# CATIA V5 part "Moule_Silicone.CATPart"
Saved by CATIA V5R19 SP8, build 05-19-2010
Part number: Moule
Material "Silicone 50": density 0.96 kg/m3, Young's modulus 6.7e+06 Pa
Material "Silicone 50": density 0.96 kg/m3, Young's modulus 6.7e+06 Pa
Bounding box of the stored display mesh (mm): x -5 to 15, y -30 to 30, z -30 to 30
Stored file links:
  D:\Documents\1_Travail\2- 2I2D\6 -  Ressources ITEC\Ressources Logiciels\Catia\Moule_Silicone.CATPart
  D:\Documents\1_Travail\3 -  Supports d'étude\Bonhomme_ITEC\Activités pédagogiques_Bonhomme ITEC\Activité_4-9.2h_Conception_moule\Activité 4-9.2h_Conception moule silicone\Bonhomme ITEC.CATPart
  C:\Program Files\Dassault Systemes\B19\win_b64\startup\materials\French\Catalog.CATMaterial
  D:\Travail\30 -  IUT\SICAM\CAPOT_BORNIER_15-04-14.CATPart
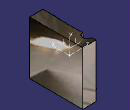
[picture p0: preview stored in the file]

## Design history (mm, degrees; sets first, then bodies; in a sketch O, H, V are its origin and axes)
Parameters
  `Epaisseur du demi-moule arrière` = 15 mm
  Hauteur = 60 mm
  Largeur = 60 mm
  `Epaisseur du demi-moule avant` = 15 mm
AxisSystem1: origin (0, 0, 0), X (0, -1, 0), Y (0, 0, 1), Z (-1, 0, 0)
Set1 "Esquisses paramétrables"
  Sketch1 "Bloc" on yz-plane, origin (0, 0, 0), H (0, 1, 0), V (0, 0, 1)
    line L1 (30, 30) -> (30, -30)
    line L2 (30, -30) -> (-30, -30)
    line L3 (-30, -30) -> (-30, 30)
    line L4 (-30, 30) -> (30, 30)
    distance L4 L2 = 60 {= Hauteur}
    distance L1 L3 = 60 {= Largeur}
    vertical: L1 V, L3 V
    horizontal: L2 H, L4 H
    equidistance: L1 L3 O, L2 L4 O
  Sketch2 "Plots de centrage" on yz-plane, origin (0, 0, 0), H (0, 1, 0), V (0, 0, 1)
    circle A1 centre (-22, 22) radius 4
    point P1 (-22, 22)
    reference projected line E1 (-30, 50) -> (-30, -50) from Sketch1.L3
    reference projected line E2 (50, 30) -> (-50, 30) from Sketch1.L4
    reference intersected line E3 through (0, 0) direction (0, 1) from zx-plane
    circle A2 centre (-22, -22) radius 4
    circle A3 centre (22, -22) radius 4
    radius A1 = 4
    distance P1 E1 = 8 {= Sketch2.radius(A1) *2}
    distance P1 E2 = 8 {= Sketch2.radius(A1) *2}
    symmetry: A1 A2 H, A2 A3 E3
  Sketch3 "Entonnoir de coulée" on yz-plane, origin (0, 0, 0), H (0, 1, 0), V (0, 0, 1)
    line L1 (22, 18.7821) -> (22, 17.2821)
    line L2 (22, 17.2821) -> (20, 17.2821)
    point P3 (20, 17.2821)
    point P4 (20, 30)
    line L3 (20, 30) -> (25, 30)
    point P5 (25, 30)
    arc A1 centre (22, 20) radius 1.2179 from (23.1994, 19.7885) to (22, 18.7821) cw
    point P6 (22, 20)
    reference projected line E1 (35, 30) -> (-35, 30) from edge [face of Pad3 from Sketch1.L4 | start face of Pad3]
    line L4 (25, 30) -> (23.1994, 19.7885)
    axis line L5 (20, 17.2821) -> (20, 43.0292)
    reference projected line E2 (30, -35) -> (30, 35) from edge [face of Pad3 from Sketch1.L1 | start face of Pad3]
    reference intersected line E3 (-40, 30) -> (40, 30) from face of Pad1 from Sketch1.L4
    length L1 = 1.5
    distance L5 E2 = 10
    angle L5 L4 = 10
    distance L5 L1 = 2
    "Radius" P5 L5 = 5
    distance P6 E3 = 10
    vertical: L1 V, L5 V
    horizontal: L2 H, L3 H
    coincidence: L3 E1, P6 L1, L5 P4
    tangency: L4 A1
  Sketch4 "Trou de coulée_Guide" on yz-plane, origin (0, 0, 0), H (0, 1, 0), V (0, 0, 1)
    point P1 (20, 17.2821)
    line L1 (20, 17.2821) -> (20, -11.6152)
    line L2 (6.6152, -25) -> (3, -25)
    point P2 (0, -25)
    line L3 (0, -22) -> (0, -18.5526)
    reference projected point E1 (20, 17.2821) from Sketch3.P3
    reference projected line E2 (-35, -30) -> (35, -30) from edge [face of Pad3 from Sketch1.L2 | start face of Pad3]
    arc A1 centre (3, -22) radius 3 from (0, -22) to (3, -25) ccw
    line L4 (18.2426, -15.8579) -> (10.8579, -23.2426)
    arc A2 centre (14, -11.6152) radius 6 from (18.2426, -15.8579) to (20, -11.6152) ccw
    arc A3 centre (6.6152, -19) radius 6 from (6.6152, -25) to (10.8579, -23.2426) ccw
    reference projected point E3 (22, -22) from edge
    distance L2 E2 = 5
    radius A1 = 3
    radius A2 = 6
    radius A3 = 6
    distance L4 E3 = 7
    angle L4 L1 = 45
    vertical: L1 V, L3 V
    coincidence: P2 V, P1 E1, L3 P2, L2 P2
    horizontal: L2 H
    tangency: A1 L3, A1 L2, A2 L4, A2 L1, A3 L2, A3 L4
  Sketch5 "Trou de coulée_Profil" on xy-plane, origin (0, 0, 0), H (1, 0, 0), V (0, 1, 0)
    circle A1 centre (0, 20) radius 2
    reference projected circle E1 centre (0, 20) radius 2 from edge [face of Groove2 from Sketch3.L1 | face of Groove2 from Sketch3.A1]
    coincidence: A1 E1
  Sketch6 "Cannaux doubles_Guide" on yz-plane, origin (0, 0, 0), H (0, 1, 0), V (0, 0, 1)
    point P1 (-8.8498, -7.3684)
    line L1 (-8.8498, -7.3684) -> (-5.9091, -18.2518)
    line L2 (-3.9924, -19.73) -> (0, -19.7581)
    point P2 (0, -19.7581)
    arc A1 centre (-3.9783, -17.7301) radius 2 from (-3.9924, -19.73) to (-5.9091, -18.2518) cw
    point P3 (-3.9924, -19.73)
    point P4 (-5.9091, -18.2518)
    reference intersected line E1 through (0, 0) direction (0, 1) from zx-plane
    point P8 (0, -19.7581)
    point P9 (3.9924, -19.73)
    line L3 (3.9924, -19.73) -> (0, -19.7581)
    point P10 (5.9091, -18.2518)
    arc A2 centre (3.9783, -17.7301) radius 2 from (3.9924, -19.73) to (5.9091, -18.2518) ccw
    point P12 (8.8498, -7.3684)
    line L4 (8.8498, -7.3684) -> (5.9091, -18.2518)
    reference projected point E2 (0, -18.7581) from Sketch7.L4
    reference projected point E3 (0, -20.7581) from Sketch7.L2
    radius A1 = 2
    coincidence: P2 V, P2 P8
    tangency: A1 L2, A1 L1
    symmetry: P2 P8 E1, P3 P9 E1, L2 L3 E1, P4 P10 E1, A1 A2 E1, P1 P12 E1, L1 L4 E1
    equidistance: E2 E3 P2
  Sketch7 "Cannaux doubles_Profil" on zx-plane, origin (0, 0, 0), H (-1, 0, 0), V (0, 0, 1)
    point P1 (0, -19.7581)
    line L1 (0.5, -18.7581) -> (0.5, -20.7581)
    line L2 (0.5, -20.7581) -> (-0.5, -20.7581)
    line L3 (-0.5, -20.7581) -> (-0.5, -18.7581)
    line L4 (-0.5, -18.7581) -> (0.5, -18.7581)
    reference intersected line E1 (0, -40) -> (0, 40) from start face of Pad3
    distance L3 L1 = 1
    distance L4 L2 = 2
    vertical: L1 V, L3 V
    horizontal: L2 H, L4 H
    equidistance: L1 L3 P1, L2 L4 P1
    coincidence: P1 E1
  Sketch8 "Event" on yz-plane, origin (0, 0, 0), H (0, 1, 0), V (0, 0, 1)
    point P1 (0, 30)
    line L1 (0, 30) -> (-12, 30)
    point P2 (-12, 30)
    point P3 (-1, 22.6077)
    line L2 (-1, 22.6077) -> (-1, 20.6077)
    point P4 (-1, 20.6077)
    line L3 (-1, 20.6077) -> (0, 20.6077)
    point P5 (0, 20.6077)
    reference projected line E1 (50, 30) -> (-50, 30) from edge [face of Pad3 from Sketch1.L4 | start face of Pad3]
    reference intersected line E2 through (0, 0) direction (0, 1) from zx-plane
    point P8 (0, 30)
    point P9 (12, 30)
    point P10 (1, 22.6077)
    point P11 (1, 20.6077)
    point P12 (0, 20.6077)
    line L4 (0, 30) -> (12, 30)
    line L5 (12, 30) -> (1, 22.6077)
    line L6 (1, 22.6077) -> (1, 20.6077)
    line L7 (1, 20.6077) -> (0, 20.6077)
    point P13 (-12, 30)
    line L8 (-12, 30) -> (-1, 22.6077)
    length L3 = 1
    length L1 = 12 {= Sketch1.distance(L4 L2) /5}
    length L2 = 2
    coincidence: P1 V, P5 V, L1 E1, P1 P8, P5 P12, P13 P2
    horizontal: L1 H, L3 H
    vertical: L2 V
    symmetry: P1 P8 E2, P2 P9 E2, P3 P10 E2, P4 P11 E2, P5 P12 E2, L1 L4 E2, L2 L6 E2, L3 L7 E2
  Sketch9 "Bloc contre moule" on end face of Pad2, origin (-5, 0, 0), H (0, 1, 0), V (0, 0, 1)
    line L1 (-35, 35) -> (35, 35)
    line L2 (35, 35) -> (35, -35)
    line L3 (35, -35) -> (-35, -35)
    line L4 (-35, -35) -> (-35, 35)
    reference projected line E1 (30, -40) -> (30, 40) from edge [face of Pad1 from Sketch1.L1 | end face of Pad1]
    reference projected line E2 (-30, 40) -> (-30, -40) from edge [face of Pad1 from Sketch1.L3 | end face of Pad1]
    reference projected line E3 (-40, -30) -> (40, -30) from edge [face of Pad1 from Sketch1.L2 | end face of Pad1]
    reference intersected line E4 through (0, 30) direction (1, 0) from face of Pad1 from Sketch1.L4
    distance E1 L2 = 5
    distance L4 E2 = 5 {= Sketch9.distance(E1 L2)}
    distance E3 L3 = 5 {= Sketch9.distance(E1 L2)}
    distance L1 E4 = 5 {= Sketch9.distance(E1 L2)}
    horizontal: L1 H, L3 H
    vertical: L2 V, L4 V
Body1 "Demi-moule Arrière" (main body), material "Silicone 50"
  Pad1 "Bloc": profile Sketch1, direction (1, 0, 0), length 15 {= `Epaisseur du demi-moule arrière`}
  Pad2 "Plots": profile Sketch2, direction (-1, 0, 0), length 5
  Draft1 "Dépouille.plots": PullDir end face of Pad2, Angle 5, SupportToDraft (face of Pad2 from Sketch2.A1; face of Pad2 from Sketch2.A2; face of Pad2 from Sketch2.A3), Neutral start face of Pad1
  Groove1 "Entonnoir de coulée": profile Sketch3, axis Sketch3.L5, angle 360
  Slot1 "Trou de coulée": profile Sketch5, centre curve Sketch4
  Slot2 "Cannaux de coulée": profile Sketch7, centre curve Sketch6
  Pocket1 "Event": profile Sketch8, direction (1, 0, 0), length 0.5
Body2 "Demi-moule Avant", material "Silicone 50"
  Pad3 "Bloc": profile Sketch1, direction (-1, 0, 0), length 15 {= `Epaisseur du demi-moule avant`}
  Pocket2 "Plots": profile Sketch2, direction (-1, 0, 0), length 6
  Draft2 "Dépouille.Plots": PullDir (-1, 0, 0), Angle -5, SupportToDraft (face of Pocket2 from Sketch2.A2; face of Pocket2 from Sketch2.A3; face of Pocket2 from Sketch2.A1), Neutral start face of Pad3
  Groove2 "Entonnir de coulée": profile Sketch3, axis Sketch3.L5, angle 360
  Slot3 "Trou de coulée": profile Sketch5, centre curve Sketch4
  Slot4 "Cannaux double": profile Sketch7, centre curve Sketch6
  Pocket3 "Event": profile Sketch8, direction (-1, 0, 0), length 0.5
Body3 "Contre moule arrière", material "Aucun"
  Plane1: type Offset, RefPlane end face of Pad2, Offset 0, reversed
  Pad4: profile Sketch9, direction (-1, 0, 0), length 2
  Sketch10 on start face of Pad4, origin (-5, 0, 0), H (0, 1, 0), V (0, 0, 1)
  Pad5: profile Sketch10, direction (1, 0, 0), up to end face of Pad1
  Body4 "Demi-moule Arrière"
    Solid1: linked copy from another document
  Remove1: tool Body4
Body5 "Contre moule Avant"
  Plane2: type Offset, RefPlane start face of Pad3, Offset 2, reversed
  Sketch11 on Plane2, origin (2, 0, 0), H (0, 1, 0), V (0, 0, 1)
  Pad6: profile Sketch11, direction (1, 0, 0), length 3
  Sketch12 on start face of Pad6, origin (2, 0, 0), H (0, -1, 0), V (0, 0, 1)
  Pad7: profile Sketch12, direction (-1, 0, 0), up to end face of Pad3
  Body6 "Demi-moule Avant"
    Solid2: linked copy from another document
  Remove2: tool Body6
Body7 "Pièce brute"
  Sketch13 on yz-plane, origin (0, 0, 0), H (0, 1, 0), V (0, 0, 1)
  Pad8: profile Sketch13, direction (1, 0, 0), up to end face of Pad1, opposite side up to end face of Pad3
  Body8 "Demi-moule Avant"
    Solid3: linked copy from another document
  Remove3: tool Body8
  Body9 "Demi-moule Arrière"
    Solid4: linked copy from another document
  Remove4: tool Body9
  Sketch14 on face of Solid3, origin (-6, 0, 0), H (0, -1, 0), V (0, 0, 1)
    circle A1 centre (-22, -22) radius 3.5626
    circle A2 centre (22, -22) radius 3.5626
    circle A3 centre (22, 22) radius 3.5626
    reference projected circle E1 centre (22, 22) radius 3.5626 from edge [face of Solid4 | face of Solid3]
    reference projected circle E2 centre (22, -22) radius 3.5626 from edge [face of Solid4 | face of Solid3]
    reference projected circle E3 centre (-22, -22) radius 3.5626 from edge [face of Solid4 | face of Solid3]
    coincidence: A3 E1, A2 E2, A1 E3
  Pocket4: profile Sketch14, direction (1, 0, 0), length 40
